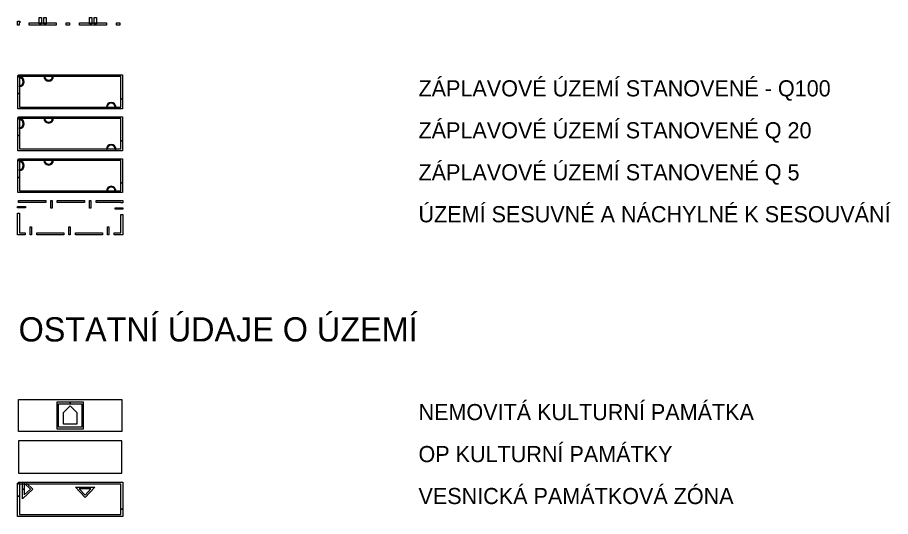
# Model space of a CAD drawing. Extents: x -475459 to -471909, y -1154716 to -1153244.
# Drawn here: x -472798.6 to -472527.8, y -1154386.8 to -1154232.2 of the extents above; entities that cross this region are included whole.
import ezdxf

# ---------------------------------------------------------------- set-up
doc = ezdxf.new("R2010")
doc.units = 0
for name, color, linetype in [('10', 7, 'Continuous'), ('pam_objekty', 7, 'Continuous'), ('porost_sklenik', 7, 'Continuous'), ('vodni_pl_rybnik', 7, 'Continuous'), ('Vrstva 13', 7, 'Continuous'), ('Vrstva 19', 7, 'Continuous'), ('Vrstva 60', 7, 'Continuous')]:
    doc.layers.add(name, color=color, linetype=linetype)

msp = doc.modelspace()

# ---------------------------------------------------------------- linework, layer by layer
at = {"layer": '10'}
for p, q in [((-472791.84, -1154234.24), (-472791.84, -1154232.24)), ((-472791.84, -1154232.24), (-472791.12, -1154232.24)), ((-472791.12, -1154234.24), (-472791.84, -1154234.24)), ((-472791.12, -1154232.24), (-472791.12, -1154234.24)), ((-472790.4, -1154234.24), (-472790.4, -1154232.24)), ((-472790.4, -1154232.24), (-472789.68, -1154232.24)), ((-472789.68, -1154234.24), (-472790.4, -1154234.24)), ((-472789.68, -1154232.24), (-472789.68, -1154234.24)), ((-472776.24, -1154234.24), (-472776.24, -1154232.24)), ((-472776.24, -1154232.24), (-472775.52, -1154232.24)), ((-472775.52, -1154234.24), (-472776.24, -1154234.24)), ((-472775.52, -1154232.24), (-472775.52, -1154234.24)), ((-472774.8, -1154234.24), (-472774.8, -1154232.24)), ((-472774.8, -1154232.24), (-472774.08, -1154232.24)), ((-472774.08, -1154234.24), (-472774.8, -1154234.24)), ((-472774.08, -1154232.24), (-472774.08, -1154234.24)), ((-472798.5, -1154291.24), (-472798.5, -1154290.84)), ((-472798.5, -1154290.84), (-472796.1, -1154290.84)), ((-472796.1, -1154290.84), (-472796.1, -1154291.24)), ((-472788.2, -1154288.94), (-472787.8, -1154288.94)), ((-472788.2, -1154291.34), (-472788.2, -1154288.94)), ((-472787.8, -1154288.94), (-472787.8, -1154291.34)), ((-472776.2, -1154288.94), (-472775.8, -1154288.94)), ((-472776.2, -1154291.34), (-472776.2, -1154288.94)), ((-472775.8, -1154288.94), (-472775.8, -1154291.34)), ((-472796.1, -1154291.24), (-472798.5, -1154291.24)), ((-472787.8, -1154291.34), (-472788.2, -1154291.34)), ((-472775.8, -1154291.34), (-472776.2, -1154291.34)), ((-472768.3, -1154291.64), (-472768.3, -1154291.24)), ((-472768.3, -1154291.24), (-472765.9, -1154291.24)), ((-472765.9, -1154291.64), (-472768.3, -1154291.64)), ((-472765.9, -1154291.24), (-472765.9, -1154291.64)), ((-472794.6, -1154299.54), (-472794.6, -1154297.14)), ((-472794.6, -1154297.14), (-472794.2, -1154297.14)), ((-472794.2, -1154297.14), (-472794.2, -1154299.54)), ((-472782.6, -1154299.54), (-472782.6, -1154297.14)), ((-472782.6, -1154297.14), (-472782.2, -1154297.14)), ((-472782.2, -1154297.14), (-472782.2, -1154299.54)), ((-472770.6, -1154299.54), (-472770.6, -1154297.14)), ((-472770.6, -1154297.14), (-472770.2, -1154297.14)), ((-472770.2, -1154297.14), (-472770.2, -1154299.54)), ((-472794.2, -1154299.54), (-472794.6, -1154299.54)), ((-472782.2, -1154299.54), (-472782.6, -1154299.54)), ((-472770.2, -1154299.54), (-472770.6, -1154299.54))]:
    msp.add_line(p, q, dxfattribs=at)
for points in [[(-472798.04, -1154234.6), (-472798.56, -1154234.6), (-472798.56, -1154233.36), (-472797.84, -1154233.36), (-472797.84, -1154233.88), (-472798.04, -1154233.88)], [(-472786.6, -1154234.6), (-472794.92, -1154234.6), (-472794.92, -1154233.88), (-472786.6, -1154233.88)], [(-472782.44, -1154234.6), (-472783.48, -1154234.6), (-472783.48, -1154233.88), (-472782.44, -1154233.88)], [(-472771, -1154234.6), (-472779.32, -1154234.6), (-472779.32, -1154233.88), (-472771, -1154233.88)], [(-472766.84, -1154234.6), (-472767.88, -1154234.6), (-472767.88, -1154233.88), (-472766.84, -1154233.88)], [(-472798.2, -1154288.94), (-472789.8, -1154288.94), (-472789.8, -1154289.54), (-472798.2, -1154289.54)], [(-472786.2, -1154288.94), (-472777.8, -1154288.94), (-472777.8, -1154289.54), (-472786.2, -1154289.54)], [(-472774.2, -1154288.94), (-472765.9, -1154288.94), (-472765.9, -1154289.64), (-472766.5, -1154289.64), (-472766.5, -1154289.54), (-472774.2, -1154289.54)], [(-472796.2, -1154299.54), (-472798.5, -1154299.54), (-472798.5, -1154292.84), (-472797.9, -1154292.84), (-472797.9, -1154298.94), (-472796.2, -1154298.94)], [(-472765.9, -1154293.24), (-472765.9, -1154299.54), (-472768.6, -1154299.54), (-472768.6, -1154298.94), (-472766.5, -1154298.94), (-472766.5, -1154293.24)], [(-472784.2, -1154299.54), (-472792.6, -1154299.54), (-472792.6, -1154298.94), (-472784.2, -1154298.94)], [(-472772.2, -1154299.54), (-472780.6, -1154299.54), (-472780.6, -1154298.94), (-472772.2, -1154298.94)]]:
    msp.add_lwpolyline(points, close=True, dxfattribs=at)
at = {"layer": 'pam_objekty'}
for p, q in [((-472784.27, -1154354.58), (-472782.22, -1154352.53)), ((-472782.22, -1154352.53), (-472780.17, -1154354.58)), ((-472782.21, -1154351.88), (-472782.21, -1154351.37)), ((-472782.2, -1154351.37), (-472782.2, -1154351.88)), ((-472784.27, -1154358.27), (-472784.27, -1154354.58)), ((-472780.17, -1154354.58), (-472780.17, -1154358.27)), ((-472780.17, -1154358.27), (-472784.27, -1154358.27))]:
    msp.add_line(p, q, dxfattribs=at)
for points in [[(-472782.21, -1154351.37), (-472786.36, -1154351.37), (-472786.36, -1154359.69), (-472778.04, -1154359.69), (-472778.04, -1154351.37), (-472782.2, -1154351.37)], [(-472782.2, -1154351.88), (-472778.55, -1154351.88), (-472778.55, -1154359.18), (-472785.85, -1154359.18), (-472785.85, -1154351.88), (-472782.21, -1154351.88)]]:
    msp.add_lwpolyline(points, dxfattribs=at)
msp.add_lwpolyline([(-472785.85, -1154351.88), (-472778.55, -1154351.88), (-472778.55, -1154359.18), (-472785.85, -1154359.18)], close=True, dxfattribs=at)
at = {"layer": 'porost_sklenik'}
for p, q in [((-472790.14, -1154250.44), (-472790.4, -1154250.44)), ((-472787.4, -1154250.44), (-472787.66, -1154250.44)), ((-472798, -1154250.64), (-472798, -1154250.9)), ((-472798, -1154253.38), (-472798, -1154253.64)), ((-472771, -1154260.04), (-472770.74, -1154260.04)), ((-472768.26, -1154260.04), (-472768, -1154260.04)), ((-472798, -1154263.64), (-472798, -1154263.9)), ((-472790.14, -1154263.44), (-472790.4, -1154263.44)), ((-472787.4, -1154263.44), (-472787.66, -1154263.44)), ((-472798, -1154266.38), (-472798, -1154266.64)), ((-472771, -1154273.04), (-472770.74, -1154273.04)), ((-472768.26, -1154273.04), (-472768, -1154273.04)), ((-472798, -1154276.64), (-472798, -1154276.9)), ((-472790.14, -1154276.44), (-472790.4, -1154276.44)), ((-472787.4, -1154276.44), (-472787.66, -1154276.44)), ((-472798, -1154279.38), (-472798, -1154279.64)), ((-472771, -1154286.04), (-472770.74, -1154286.04)), ((-472768.26, -1154286.04), (-472768, -1154286.04))]:
    msp.add_line(p, q, dxfattribs=at)
for points in [[(-472798.46, -1154255.84), (-472798.46, -1154250.24), (-472797.94, -1154250.24), (-472797.94, -1154255.84)], [(-472798.2, -1154249.98), (-472765.94, -1154249.98), (-472765.94, -1154257.44), (-472766.46, -1154257.44), (-472766.46, -1154250.5), (-472798.2, -1154250.5)], [(-472765.94, -1154257.44), (-472765.94, -1154260.5), (-472798.46, -1154260.5), (-472798.46, -1154255.84), (-472797.94, -1154255.84), (-472797.94, -1154259.98), (-472766.46, -1154259.98), (-472766.46, -1154257.44)], [(-472798.46, -1154268.84), (-472798.46, -1154263.24), (-472797.94, -1154263.24), (-472797.94, -1154268.84)], [(-472798.2, -1154262.98), (-472765.94, -1154262.98), (-472765.94, -1154270.44), (-472766.46, -1154270.44), (-472766.46, -1154263.5), (-472798.2, -1154263.5)], [(-472765.94, -1154270.44), (-472765.94, -1154273.5), (-472798.46, -1154273.5), (-472798.46, -1154268.84), (-472797.94, -1154268.84), (-472797.94, -1154272.98), (-472766.46, -1154272.98), (-472766.46, -1154270.44)], [(-472798.46, -1154281.84), (-472798.46, -1154276.24), (-472797.94, -1154276.24), (-472797.94, -1154281.84)], [(-472798.2, -1154275.98), (-472765.94, -1154275.98), (-472765.94, -1154283.44), (-472766.46, -1154283.44), (-472766.46, -1154276.5), (-472798.2, -1154276.5)], [(-472765.94, -1154283.44), (-472765.94, -1154286.5), (-472798.46, -1154286.5), (-472798.46, -1154281.84), (-472797.94, -1154281.84), (-472797.94, -1154285.98), (-472766.46, -1154285.98), (-472766.46, -1154283.44)]]:
    msp.add_lwpolyline(points, close=True, dxfattribs=at)
for centre, radius, start, end in [((-472788.9, -1154250.44), 1.5, 180.0001, 359.9997), ((-472788.9, -1154250.44), 1.24, 180.0001, 359.9997), ((-472798, -1154252.14), 1.5, 270.0001, 89.9997), ((-472798, -1154252.14), 1.24, 270.0001, 89.9997), ((-472769.5, -1154260.04), 1.5, 0.0001, 179.9997), ((-472769.5, -1154260.04), 1.24, 0.0001, 179.9997), ((-472798, -1154265.14), 1.5, 270.0001, 89.9997), ((-472798, -1154265.14), 1.24, 270.0001, 89.9997), ((-472788.9, -1154263.44), 1.5, 180.0001, 359.9997), ((-472788.9, -1154263.44), 1.24, 180.0001, 359.9997), ((-472769.5, -1154273.04), 1.5, 0.0001, 179.9997), ((-472769.5, -1154273.04), 1.24, 0.0001, 179.9997), ((-472798, -1154278.14), 1.5, 270.0001, 89.9997), ((-472798, -1154278.14), 1.24, 270.0001, 89.9997), ((-472788.9, -1154276.44), 1.5, 180.0001, 359.9997), ((-472788.9, -1154276.44), 1.24, 180.0001, 359.9997), ((-472769.5, -1154286.04), 1.5, 0.0001, 179.9997), ((-472769.5, -1154286.04), 1.24, 0.0001, 179.9997)]:
    msp.add_arc(centre, radius, start, end, dxfattribs=at)
at = {"layer": 'vodni_pl_rybnik'}
for p, q in [((-472777.62, -1154377.73), (-472777.62, -1154378.25)), ((-472777.6, -1154378.25), (-472777.6, -1154377.73)), ((-472796.48, -1154378.33), (-472797, -1154378.33)), ((-472797, -1154378.35), (-472796.48, -1154378.35))]:
    msp.add_line(p, q, dxfattribs=at)
for points in [[(-472798.5, -1154380.53), (-472798.5, -1154376.53), (-472797.9, -1154376.53), (-472797.9, -1154380.53)], [(-472798.2, -1154376.23), (-472765.9, -1154376.23), (-472765.9, -1154384.53), (-472766.5, -1154384.53), (-472766.5, -1154376.83), (-472798.2, -1154376.83)], [(-472765.9, -1154384.53), (-472765.9, -1154386.83), (-472798.5, -1154386.83), (-472798.5, -1154380.53), (-472797.9, -1154380.53), (-472797.9, -1154386.23), (-472766.5, -1154386.23), (-472766.5, -1154384.53)]]:
    msp.add_lwpolyline(points, close=True, dxfattribs=at)
for points in [[(-472795.72, -1154376.53), (-472793.8, -1154378.33), (-472797, -1154381.33), (-472797, -1154378.35)], [(-472797, -1154378.33), (-472797, -1154376.53)], [(-472796.48, -1154378.35), (-472796.48, -1154380.13), (-472794.56, -1154378.33), (-472796.48, -1154376.53), (-472796.48, -1154378.33)], [(-472777.6, -1154377.73), (-472774.6, -1154377.73), (-472777.6, -1154380.93), (-472780.6, -1154377.73), (-472777.62, -1154377.73)], [(-472777.62, -1154378.25), (-472779.4, -1154378.25), (-472777.6, -1154380.17), (-472775.8, -1154378.25), (-472777.6, -1154378.25)]]:
    msp.add_lwpolyline(points, dxfattribs=at)
at = {"layer": 'Vrstva 13'}
msp.add_lwpolyline([(-472798.2, -1154350.53), (-472766.2, -1154350.53), (-472766.2, -1154360.53), (-472798.2, -1154360.53)], close=True, dxfattribs=at)
at = {"layer": 'Vrstva 19'}
msp.add_lwpolyline([(-472798.2, -1154363.42), (-472798.2, -1154373.42), (-472766.2, -1154373.42), (-472766.2, -1154363.42)], close=True, dxfattribs=at)

# ---------------------------------------------------------------- texts
at = {"layer": 'Vrstva 60'}
for s, height, p in [('ZÁPLAVOVÉ ÚZEMÍ STANOVENÉ - Q100', 5, (-472674.2, -1154256.69)), ('ZÁPLAVOVÉ ÚZEMÍ STANOVENÉ Q 20', 5, (-472674.2, -1154269.69)), ('ZÁPLAVOVÉ ÚZEMÍ STANOVENÉ Q 5', 5, (-472674.2, -1154282.69)), ('ÚZEMÍ SESUVNÉ A NÁCHYLNÉ K SESOUVÁNÍ', 5, (-472674.2, -1154295.69)), ('OSTATNÍ ÚDAJE O ÚZEMÍ', 7.5, (-472798.2, -1154332.61)), ('NEMOVITÁ KULTURNÍ PAMÁTKA', 5, (-472674.2, -1154356.98)), ('OP KULTURNÍ PAMÁTKY', 5, (-472674.2, -1154369.98)), ('VESNICKÁ PAMÁTKOVÁ ZÓNA', 5, (-472674.2, -1154382.98))]:
    msp.add_text(s, height=height, dxfattribs=at).set_placement(p)

doc.saveas('drawing.dxf')
